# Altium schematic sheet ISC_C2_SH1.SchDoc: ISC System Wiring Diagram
size B; DrawnBy: Filiberto Clara; Engineer: Filiberto Clara; Organization: LIGO Laboratory; Address1: California Institute of Technology; Address2: Massachusetts Institute of Technology; SheetNumber: 3; SheetTotal: 37
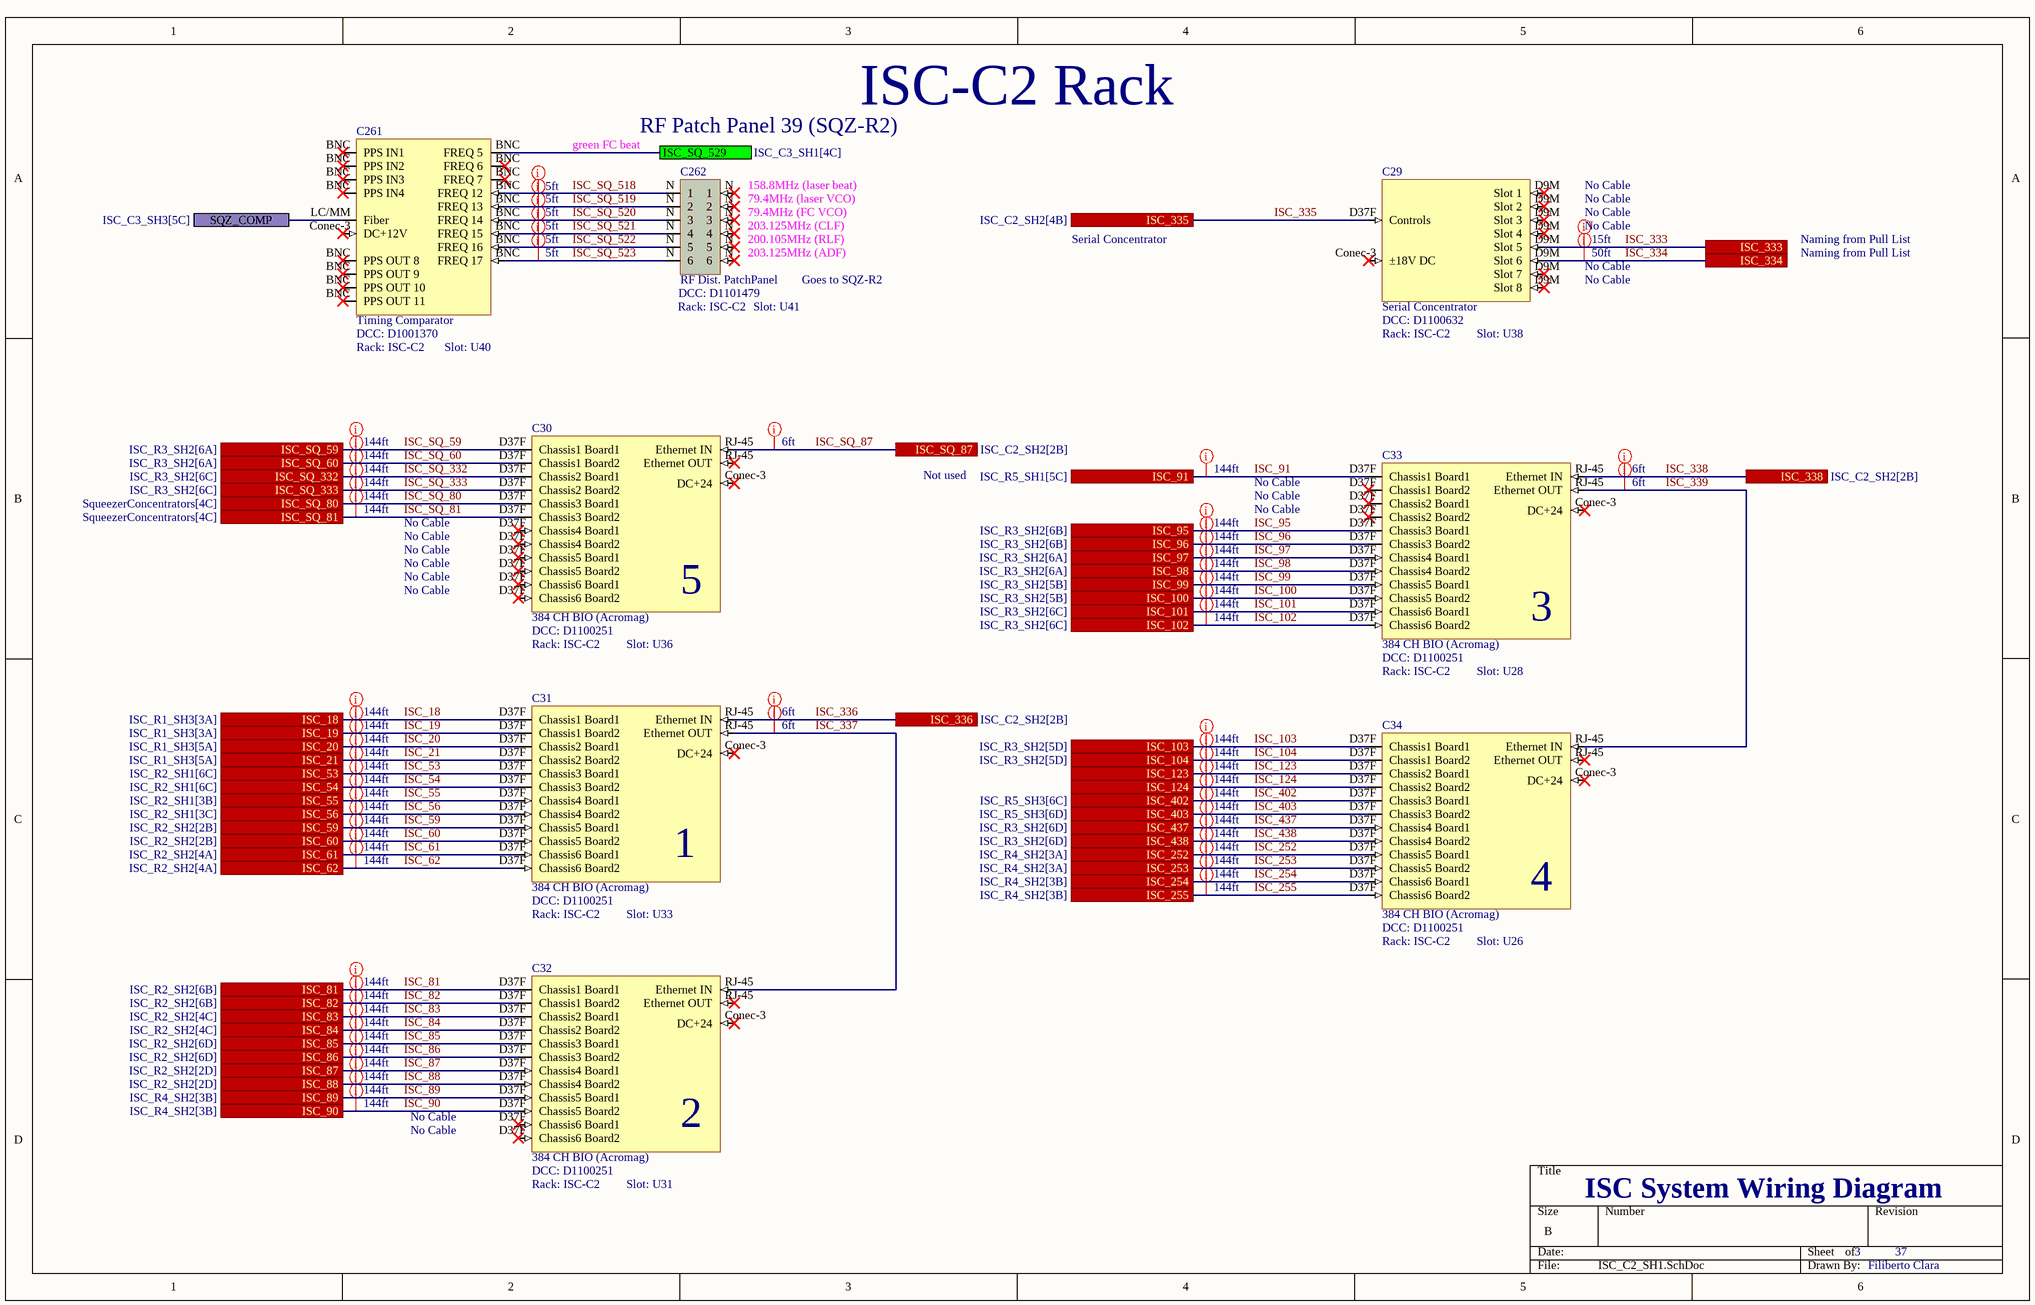
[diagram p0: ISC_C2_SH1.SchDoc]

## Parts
C29  Serial Concentrator  DCC: D1100632  Rack: ISC-C2  Slot: U38
C30  384 CH BIO (Acromag)  DCC: D1100251  Rack: ISC-C2  Slot: U36
C31  384 CH BIO (Acromag)  DCC: D1100251  Rack: ISC-C2  Slot: U33
C32  384 CH BIO (Acromag)  DCC: D1100251  Rack: ISC-C2  Slot: U31
C33  384 CH BIO (Acromag)  DCC: D1100251  Rack: ISC-C2  Slot: U28
C34  384 CH BIO (Acromag)  DCC: D1100251  Rack: ISC-C2  Slot: U26
C261  Timing Comparator  DCC: D1001370  Rack: ISC-C2  Slot: U40
C262  RF Dist. PatchPanel  DCC: D1101479  Rack: ISC-C2  Slot: U41

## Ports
ISC_18 (see ISC_R1_SH3[3A]), ISC_19 (see ISC_R1_SH3[3A]), ISC_20 (see ISC_R1_SH3[5A]), ISC_21 (see ISC_R1_SH3[5A]), ISC_53 (see ISC_R2_SH1[6C]), ISC_54 (see ISC_R2_SH1[6C]), ISC_55 (see ISC_R2_SH1[3B]), ISC_56 (see ISC_R2_SH1[3C]), ISC_59 (see ISC_R2_SH2[2B]), ISC_60 (see ISC_R2_SH2[2B]), ISC_61 (see ISC_R2_SH2[4A]), ISC_62 (see ISC_R2_SH2[4A]), ISC_81 (see ISC_R2_SH2[6B]), ISC_82 (see ISC_R2_SH2[6B]), ISC_83 (see ISC_R2_SH2[4C]), ISC_84 (see ISC_R2_SH2[4C]), ISC_85 (see ISC_R2_SH2[6D]), ISC_86 (see ISC_R2_SH2[6D]), ISC_87 (see ISC_R2_SH2[2D]), ISC_88 (see ISC_R2_SH2[2D]), ISC_89 (see ISC_R4_SH2[3B]), ISC_90 (see ISC_R4_SH2[3B]), ISC_91 (see ISC_R5_SH1[5C]), ISC_95 (see ISC_R3_SH2[6B]), ISC_96 (see ISC_R3_SH2[6B]), ISC_97 (see ISC_R3_SH2[6A]), ISC_98 (see ISC_R3_SH2[6A]), ISC_99 (see ISC_R3_SH2[5B]), ISC_100 (see ISC_R3_SH2[5B]), ISC_101 (see ISC_R3_SH2[6C]), ISC_102 (see ISC_R3_SH2[6C]), ISC_103 (see ISC_R3_SH2[5D]), ISC_104 (see ISC_R3_SH2[5D]), ISC_123, ISC_124, ISC_252 (see ISC_R4_SH2[3A]), ISC_253 (see ISC_R4_SH2[3A]), ISC_254 (see ISC_R4_SH2[3B]), ISC_255 (see ISC_R4_SH2[3B]), ISC_333, ISC_334, ISC_335 (see ISC_C2_SH2[4B]), ISC_336 (see ISC_C2_SH2[2B]), ISC_338 (see ISC_C2_SH2[2B]), ISC_402 (see ISC_R5_SH3[6C]), ISC_403 (see ISC_R5_SH3[6D]), ISC_437 (see ISC_R3_SH2[6D]), ISC_438 (see ISC_R3_SH2[6D]), ISC_SQ_59 (see ISC_R3_SH2[6A]), ISC_SQ_60 (see ISC_R3_SH2[6A]), ISC_SQ_80 (see SqueezerConcentrators[4C]), ISC_SQ_81 (see SqueezerConcentrators[4C]), ISC_SQ_87 (see ISC_C2_SH2[2B]), ISC_SQ_332 (see ISC_R3_SH2[6C]), ISC_SQ_333 (see ISC_R3_SH2[6C]), ISC_SQ_529 (see ISC_C3_SH1[4C]), SQZ_COMP (see ISC_C3_SH3[5C])

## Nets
ISC_18: C31.D37F(Chassis1_Board1) ; port ISC_18
ISC_19: C31.D37F(Chassis1_Board2) ; port ISC_19
ISC_20: C31.D37F(Chassis2_Board1) ; port ISC_20
ISC_21: C31.D37F(Chassis2_Board2) ; port ISC_21
ISC_53: C31.D37F(Chassis3_Board1) ; port ISC_53
ISC_54: C31.D37F(Chassis3_Board2) ; port ISC_54
ISC_55: C31.D37F(Chassis4_Board1) ; port ISC_55
ISC_56: C31.D37F(Chassis4_Board2) ; port ISC_56
ISC_59: C31.D37F(Chassis5_Board1) ; port ISC_59
ISC_60: C31.D37F(Chassis5_Board2) ; port ISC_60
ISC_61: C31.D37F(Chassis6_Board1) ; port ISC_61
ISC_62: C31.D37F(Chassis6_Board2) ; port ISC_62
ISC_81: C32.D37F(Chassis1_Board1) ; port ISC_81
ISC_82: C32.D37F(Chassis1_Board2) ; port ISC_82
ISC_83: C32.D37F(Chassis2_Board1) ; port ISC_83
ISC_84: C32.D37F(Chassis2_Board2) ; port ISC_84
ISC_85: C32.D37F(Chassis3_Board1) ; port ISC_85
ISC_86: C32.D37F(Chassis3_Board2) ; port ISC_86
ISC_87: C32.D37F(Chassis4_Board1) ; port ISC_87
ISC_88: C32.D37F(Chassis4_Board2) ; port ISC_88
ISC_89: C32.D37F(Chassis5_Board1) ; port ISC_89
ISC_90: C32.D37F(Chassis5_Board2) ; port ISC_90
ISC_91: C33.D37F(Chassis1_Board1) ; port ISC_91
ISC_95: C33.D37F(Chassis3_Board1) ; port ISC_95
ISC_96: C33.D37F(Chassis3_Board2) ; port ISC_96
ISC_97: C33.D37F(Chassis4_Board1) ; port ISC_97
ISC_98: C33.D37F(Chassis4_Board2) ; port ISC_98
ISC_99: C33.D37F(Chassis5_Board1) ; port ISC_99
ISC_100: C33.D37F(Chassis5_Board2) ; port ISC_100
ISC_101: C33.D37F(Chassis6_Board1) ; port ISC_101
ISC_102: C33.D37F(Chassis6_Board2) ; port ISC_102
ISC_103: C34.D37F(Chassis1_Board1) ; port ISC_103
ISC_104: C34.D37F(Chassis1_Board2) ; port ISC_104
ISC_123: C34.D37F(Chassis2_Board1) ; port ISC_123
ISC_124: C34.D37F(Chassis2_Board2) ; port ISC_124
ISC_252: C34.D37F(Chassis5_Board1) ; port ISC_252
ISC_253: C34.D37F(Chassis5_Board2) ; port ISC_253
ISC_254: C34.D37F(Chassis6_Board1) ; port ISC_254
ISC_255: C34.D37F(Chassis6_Board2) ; port ISC_255
ISC_333: C29.D9M(Slot_1) ; port ISC_333
ISC_334: C29.D9M(Slot_6) ; port ISC_334
ISC_335: C29.D37F(Controls) ; port ISC_335
ISC_336: C31.RJ-45(Ethernet_IN) ; port ISC_336
ISC_337: C31.RJ-45(Ethernet_OUT) C32.RJ-45(Ethernet_IN)
ISC_338: C33.RJ-45(Ethernet_IN) ; port ISC_338
ISC_339: C33.RJ-45(Ethernet_OUT) C34.RJ-45(Ethernet_IN)
ISC_402: C34.D37F(Chassis3_Board1) ; port ISC_402
ISC_403: C34.D37F(Chassis3_Board2) ; port ISC_403
ISC_437: C34.D37F(Chassis4_Board1) ; port ISC_437
ISC_438: C34.D37F(Chassis4_Board2) ; port ISC_438
ISC_SQ_59: C30.D37F(Chassis1_Board1) ; port ISC_SQ_59
ISC_SQ_60: C30.D37F(Chassis1_Board2) ; port ISC_SQ_60
ISC_SQ_80: C30.D37F(Chassis3_Board1) ; port ISC_SQ_80
ISC_SQ_81: C30.D37F(Chassis3_Board2) ; port ISC_SQ_81
ISC_SQ_87: C30.RJ-45(Ethernet_IN) ; port ISC_SQ_87
ISC_SQ_332: C30.D37F(Chassis2_Board1) ; port ISC_SQ_332
ISC_SQ_333: C30.D37F(Chassis2_Board2) ; port ISC_SQ_333
ISC_SQ_518: C261.BNC(FREQ_12) C262.N(1)
ISC_SQ_519: C261.BNC(FREQ_13) C262.N(2)
ISC_SQ_520: C261.BNC(FREQ_14) C262.N(3)
ISC_SQ_521: C261.BNC(FREQ_15) C262.N(4)
ISC_SQ_522: C261.BNC(FREQ_16) C262.N(5)
ISC_SQ_523: C261.BNC(FREQ_17) C262.N(6)
ISC_SQ_529: C261.BNC(PPS_IN1) ; port ISC_SQ_529
SQZ_COMP: C261.LC/MM(Fiber) ; port SQZ_COMP

Not connected (* = marked no-connect by the designer): C29 Conec-3(±18V_DC)*; C30 Conec-3(DC+24)*; C31 Conec-3(DC+24)*; C32 Conec-3(DC+24)*; C33 Conec-3(DC+24)*; C34 Conec-3(DC+24)*; C261 Conec-3(DC+12V)*

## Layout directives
Length: 144ft: ISC_18, ISC_19, ISC_20, ISC_21, ISC_53, ISC_54, ISC_55, ISC_56, ISC_59, ISC_60, ISC_61, ISC_62, ISC_81, ISC_82, ISC_83, ISC_84, ISC_85, ISC_86, ISC_87, ISC_88, ISC_89, ISC_90, ISC_91, ISC_95, ISC_96, ISC_97, ISC_98, ISC_99, ISC_100, ISC_101, ISC_102, ISC_103, ISC_104, ISC_123, ISC_124, ISC_252, ISC_253, ISC_254, ISC_255, ISC_402, ISC_403, ISC_437, ISC_438, ISC_SQ_59, ISC_SQ_60, ISC_SQ_80, ISC_SQ_81, ISC_SQ_332, ISC_SQ_333
Length: 6ft: ISC_336, ISC_337, ISC_338, ISC_339, ISC_SQ_87
Length: 15ft: ISC_333
Length: 50ft: ISC_334
Length: 5ft: ISC_SQ_518, ISC_SQ_519, ISC_SQ_520, ISC_SQ_521, ISC_SQ_522, ISC_SQ_523

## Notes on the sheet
- ISC-C2 Rack
- (near C262) green FC beat
- RF Patch Panel 39 (SQZ-R2)
- (near C262) 158.8MHz (laser beat)
- (near C262) 79.4MHz (laser VCO)
- (near C262) 203.125MHz (CLF)
- (near C262) 79.4MHz (FC VCO)
- (near C262) 200.105MHz (RLF)
- Serial Concentrator
- No Cable
- Naming from Pull List
- (near C262) 203.125MHz (ADF)
- Goes to SQZ-R2
- Not used
- (near C30) 5
- (near C33) 3
- (near C31) 1
- (near C34) 4
- (near C32) 2

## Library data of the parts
C29 = Serial Concentrator: Serial: Sxxxxxxx; System: ISC
C30-C34 = 384 CH BIO (Acromag): Serial: Sxxxxxxx; System: ISC
C261 = Timing Comparator: Serial: Sxxxxxxx; System: ISC
C262 = RF Dist. PatchPanel: Serial: Sxxxxxxx; System: ISC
